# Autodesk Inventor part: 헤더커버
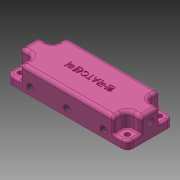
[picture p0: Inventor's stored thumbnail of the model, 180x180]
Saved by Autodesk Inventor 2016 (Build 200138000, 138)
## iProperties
Created: 2015-11
Part Number: 헤더커버
Material: 알루미늄 6061
Document SubType Name: Modeling
Designer: mduedu
Density: 2.71 g/cm^3
Appearance: 분홍색
Mass: 168.165 g
Surface Area: 162.633 cm^2
Volume: 62.0536 cm^3
Author: mduedu
## Parameters: d0 = 105 mm, d3 = 0, d4 = 12 mm, d5 = 12 mm, d6 = 13 mm, d7 = 0, d8 = 5 mm, d9 = 1 mm, d10 = 5 mm, d11 = 2 mm, d12 = 3 mm, d13 = 6 mm, d14 = 6 mm, d15 = 4.5 mm, d16 = 6 mm, d17 = 4 mm, d18 = 2 mm, d19 = 90 deg, d20 = 8 mm, d21 = 118 deg, d22 = 24.5 mm, d23 = 24.5 mm, d24 = 24.5 mm, d25 = 32 mm, d26 = 32 mm, d27 = 9 mm, d28 = 0, d29 = 5 mm, d32 = 120 deg, d34 = 12 mm, d35 = 8 mm, d38 = 12 mm, d39 = 120 deg, d40 = 8 mm, d43 = 5.944 mm, d44 = 6.886 mm, d45 = 0.62479 mm, d46 = 5.959 mm, d47 = 4 mm, d48 = 2 mm, d49 = 90 deg, d50 = 6.9 mm, d51 = 0, d54 = 5.944 mm, d55 = 6.886 mm, d56 = 0.62479 mm, d57 = 5.959 mm, d58 = 4 mm, d59 = 2 mm, d60 = 90 deg, d61 = 6.9 mm, d62 = 0, d65 = 5.944 mm, d66 = 6.886 mm, d67 = 0.62479 mm, d68 = 5.959 mm, d69 = 4 mm, d70 = 2 mm, d71 = 90 deg, d72 = 6.9 mm, d73 = 0, d74 = 0, d75 = 0, d76 = 0, d77 = 6 mm, d78 = 5.944 mm, d79 = 6.886 mm, d80 = 0.62479 mm, d81 = 5.959 mm, d82 = 4 mm, d83 = 2 mm, d84 = 90 deg, d85 = 6.9 mm, d86 = 0, d87 = 8 mm, d88 = 0, d89 = 0.5 mm, d90 = 0, d91 = 0, d92 = 0, d93 = 0
